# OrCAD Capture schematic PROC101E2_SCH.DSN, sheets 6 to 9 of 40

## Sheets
6 29. CAN & DISPLAY INTERFACE: size C; title: CAN & DISPLAY INTERFACE; note: MS_TI_MAXIE_APPLICATION_CARD_SCH_REVA
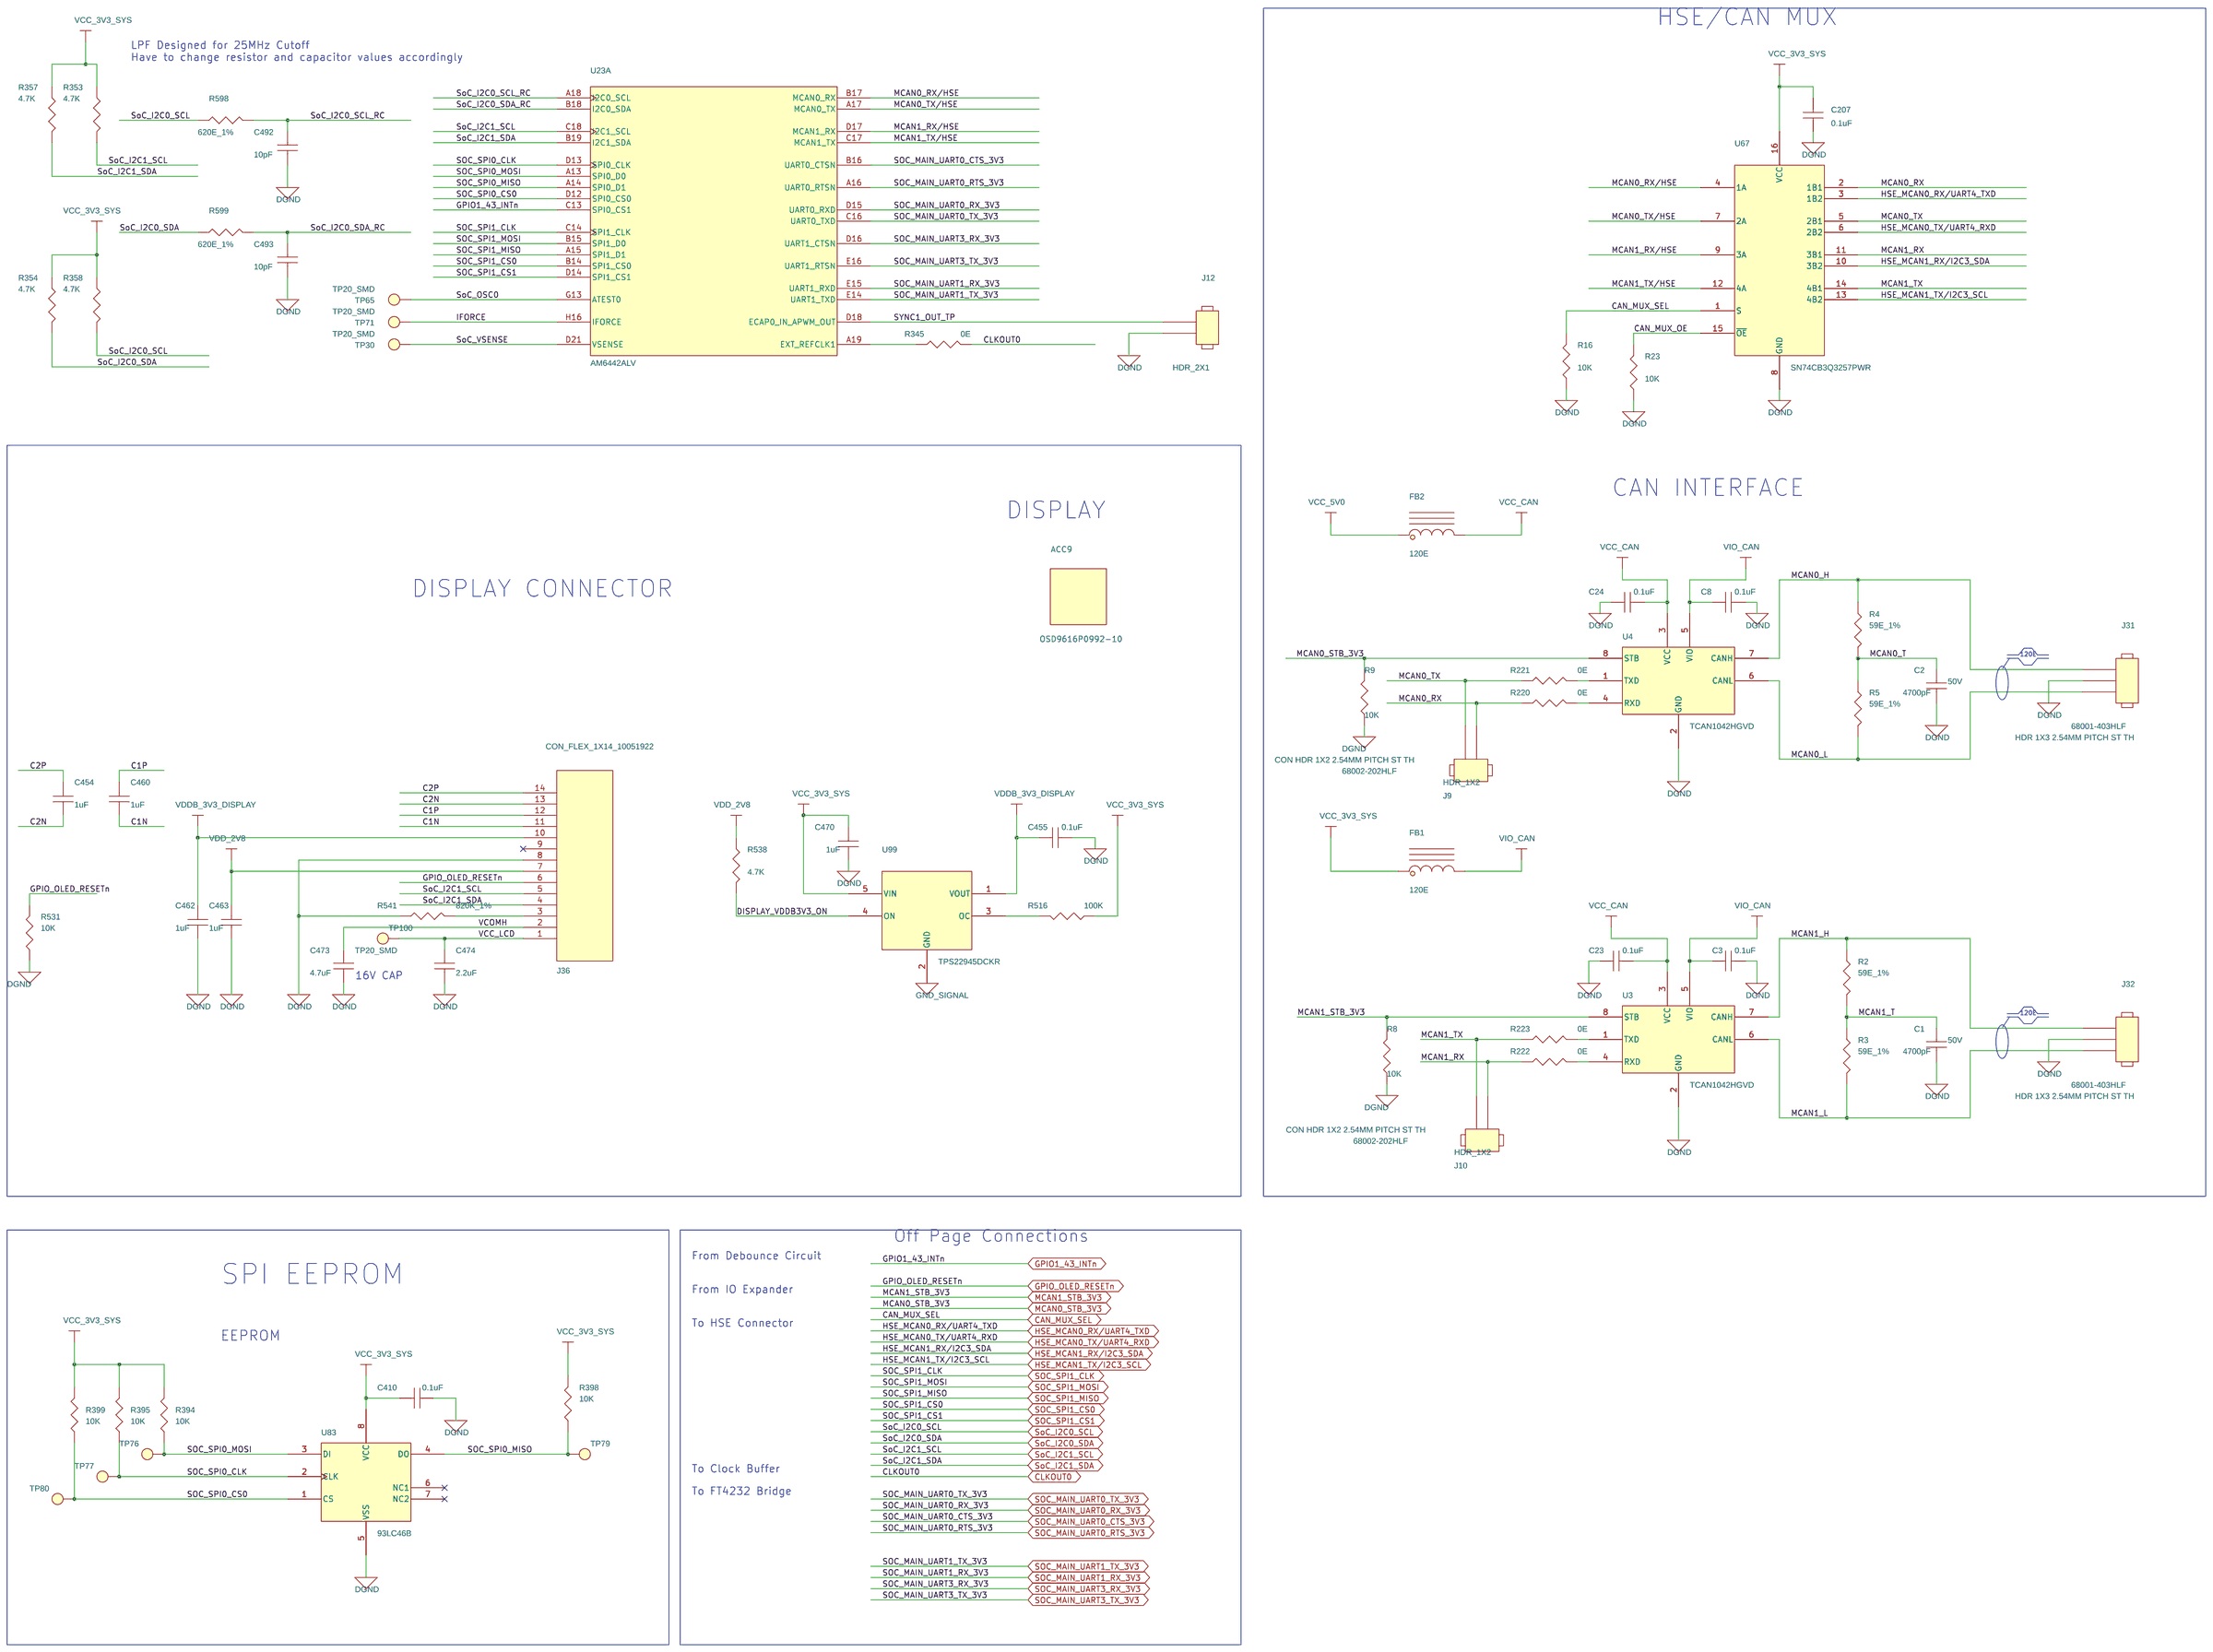
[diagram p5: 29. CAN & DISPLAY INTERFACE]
7 32.ETHERNET LED's&ADC CONNECTOR: size C; title: ETHERNET LEDs
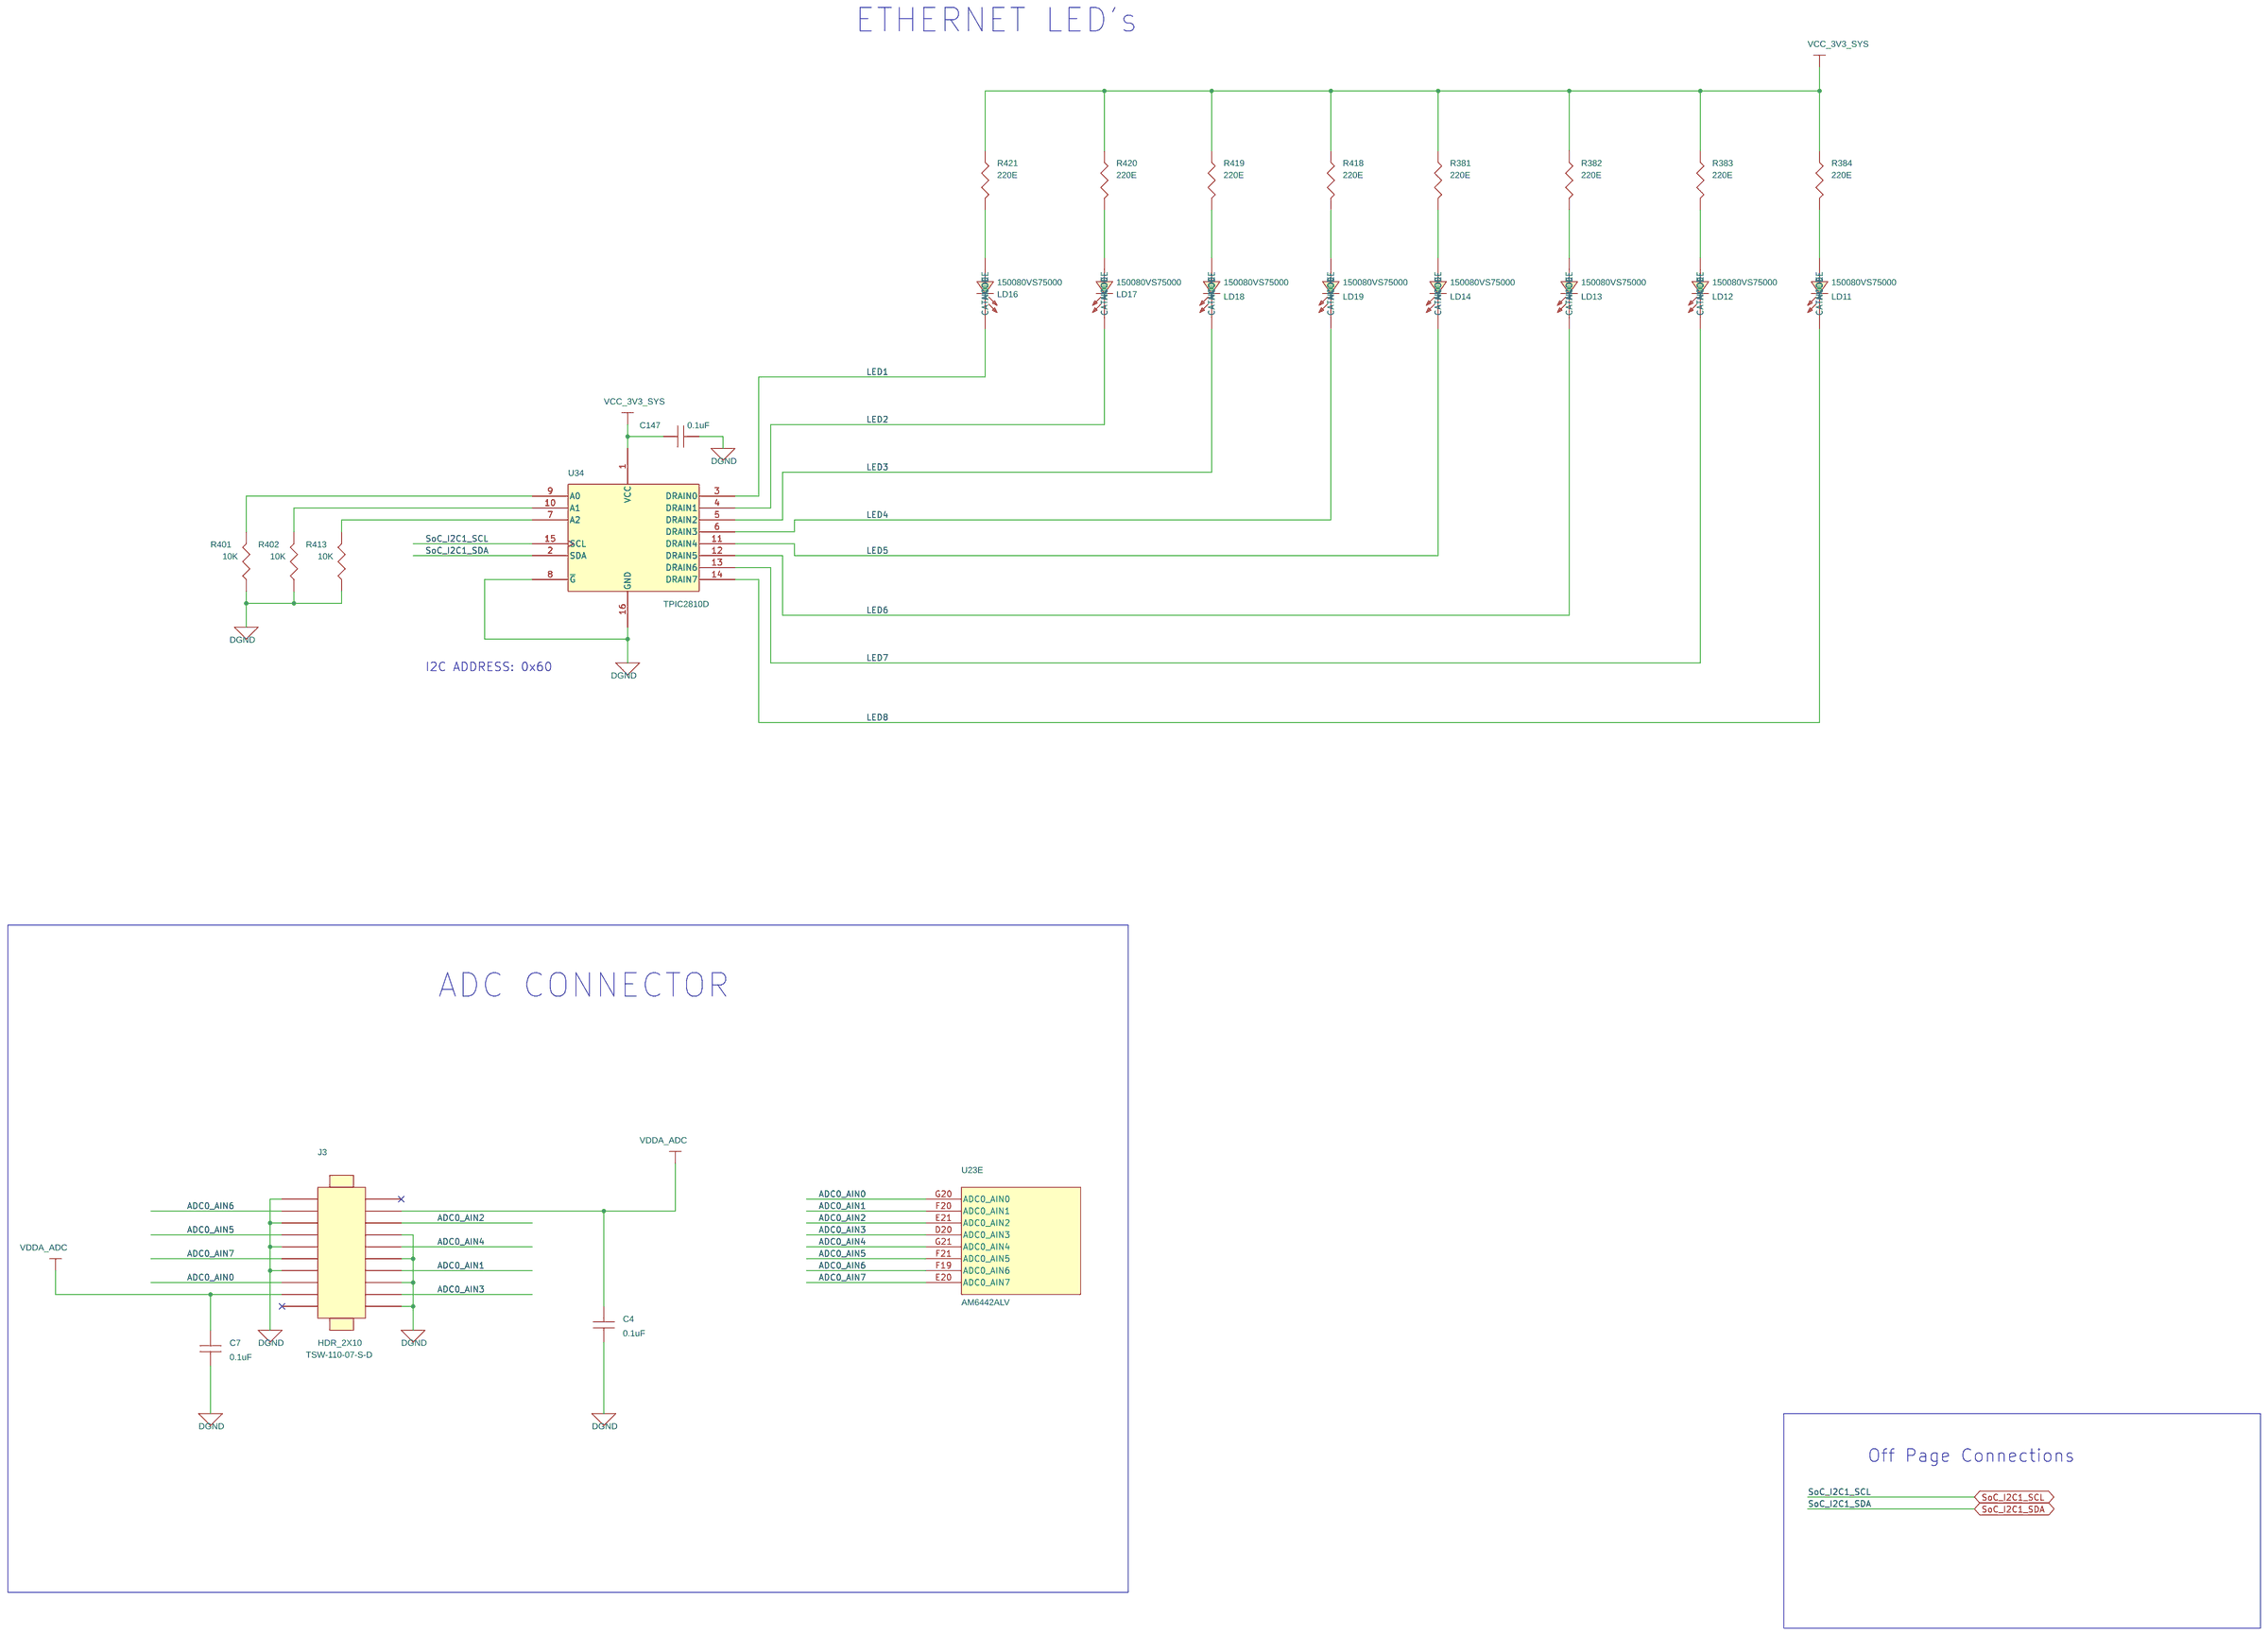
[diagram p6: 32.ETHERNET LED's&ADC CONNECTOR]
8 36. MAIN INPUT 12V DC: size C; title: MAIN 12V POWERSUPPLY
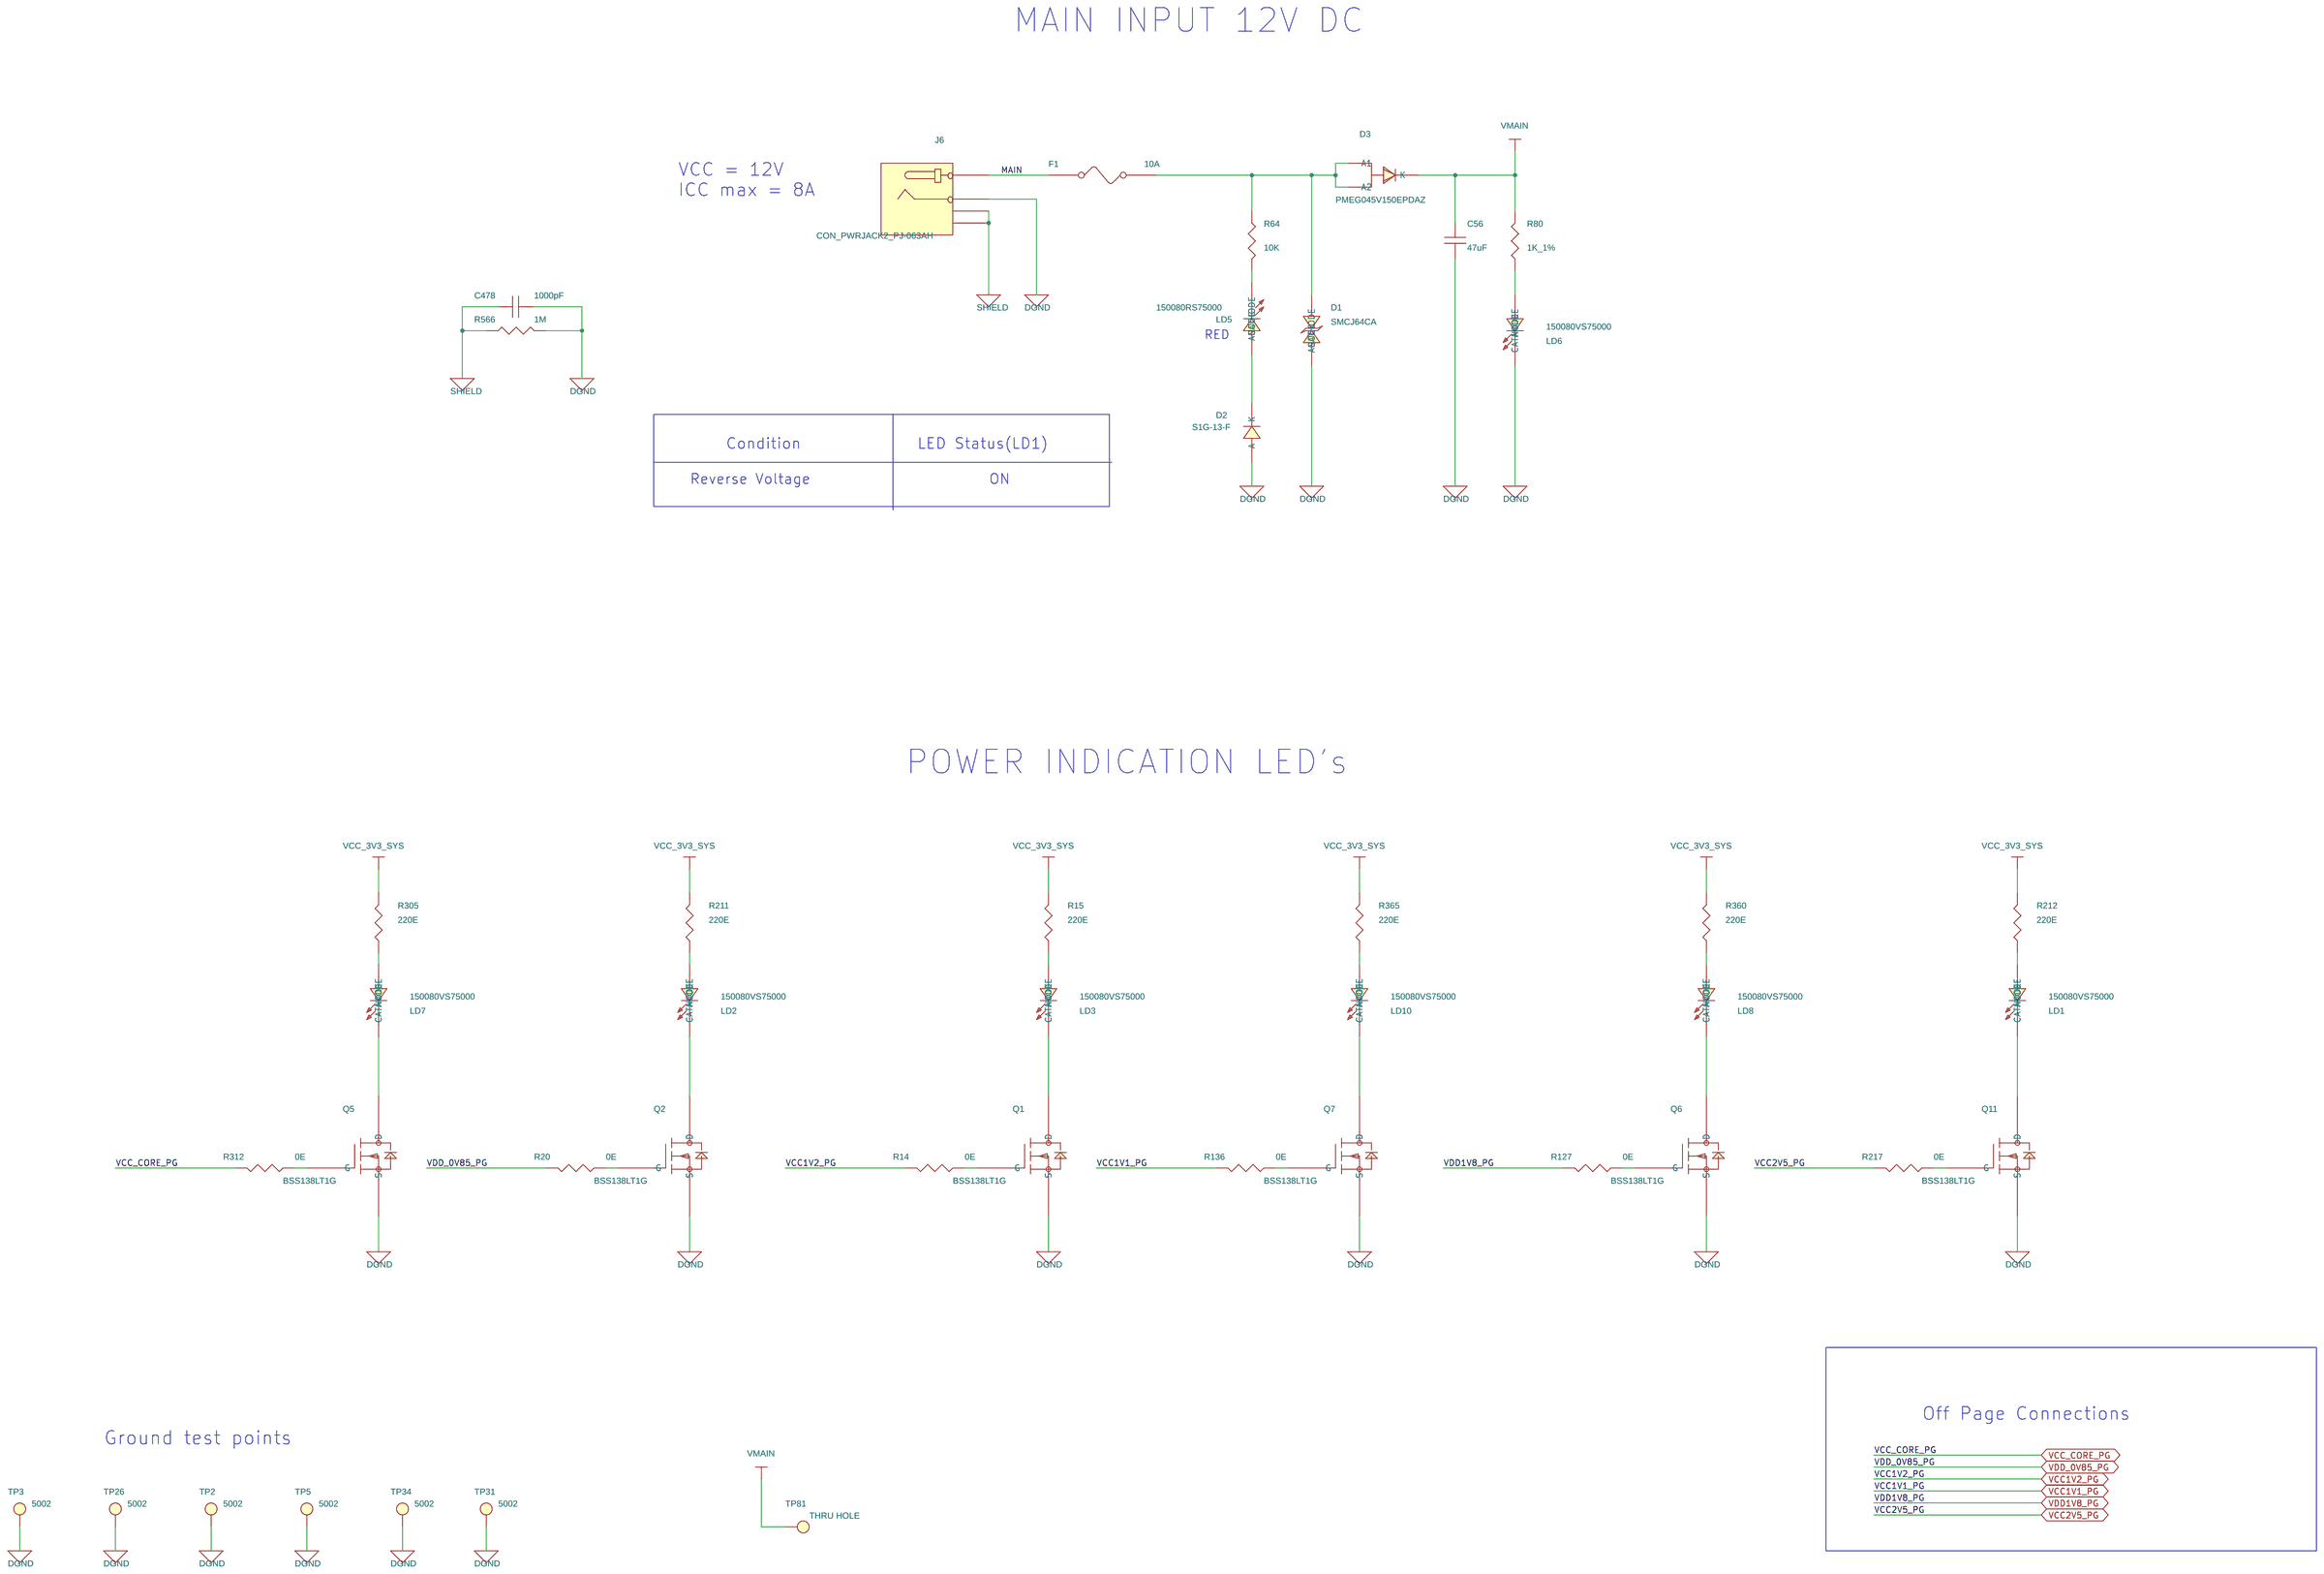
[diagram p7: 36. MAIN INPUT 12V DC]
9 11.SOC VSS: size C; title: SOC VSS
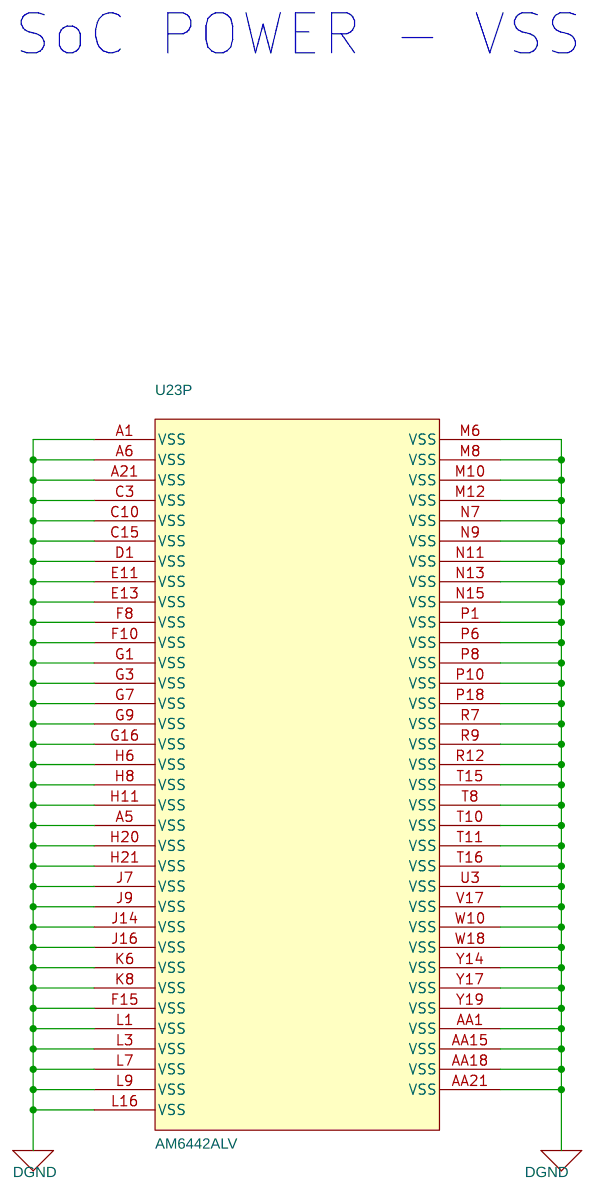
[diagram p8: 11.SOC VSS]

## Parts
sheet 11.SOC VSS
U23  AM6442ALV  [FCBGA441_31-49_680X680_2-6]  (sections A,B,C,D,E,F,G,H,I,J,K,L,M,N,O,P)
sheet 29. CAN & DISPLAY INTERFACE
ACC9  OSD9616P0992-10  [NA]
C1  4700pF  [CAP0402_0-75]
C2  4700pF  [CAP0402_0-75]
C3  0.1uF  [CAP0402_0-75]
C8  0.1uF  [CAP0402_0-75]
C23  0.1uF  [CAP0402_0-75]
C24  0.1uF  [CAP0402_0-75]
C207  0.1uF  [CAP0402_0-75]
C410  0.1uF  [CAP0402_0-75]
C454  1uF  [CAP0402_0-75]
C455  0.1uF  [CAP0402_0-75]
C460  1uF  [CAP0402_0-75]
C462  1uF  [CAP0402_0-75]
C463  1uF  [CAP0402_0-75]
C470  1uF  [CAP0402_0-75]
C473  4.7uF  [CAP0603_1]
C474  2.2uF  [CAP0603_1]
C492  10pF  [CAP0402_0-75]
C493  10pF  [CAP0402_0-75]
FB1  120E  [IND0603_1]
FB2  120E  [IND0603_1]
J9  HDR_1X2  [HDR_1X2_68002-202_S_T_8-6]
J10  HDR_1X2  [HDR_1X2_68002-202_S_T_8-6]
J12  HDR_2X1  [HDR_2X1_100_S_T]
J31  HDR_1X3  [HDR_3X1_100_S_T]
J32  HDR_1X3  [HDR_3X1_100_S_T]
J36  CON_FLEX_1X14_10051922  [CON_FLEX1X14_10051922_S_R_S]
R2  59E_1%  [RES0402_0-5]
R3  59E_1%  [RES0402_0-5]
R4  59E_1%  [RES0402_0-5]
R5  59E_1%  [RES0402_0-5]
R8  10K  [RES0402_0-5]
R9  10K  [RES0402_0-5]
R16  10K  [RES0402_0-5]
R23  10K  [RES0402_0-5]
R220  0E  [RES0402_0-5]
R221  0E  [RES0402_0-5]
R222  0E  [RES0402_0-5]
R223  0E  [RES0402_0-5]
R345  0E  [RES0402_0-5]
R353  4.7K  [RES0402_0-5]
R354  4.7K  [RES0402_0-5]
R357  4.7K  [RES0402_0-5]
R358  4.7K  [RES0402_0-5]
R394  10K  [RES0402_0-5]
R395  10K  [RES0402_0-5]
R398  10K  [RES0402_0-5]
R399  10K  [RES0402_0-5]
R516  100K  [RES0402_0-5]
R531  10K  [RES0402_0-5]
R538  4.7K  [RES0402_0-5]
R541  820K_1%  [RES0402_0-5]
R598  620E_1%  [RES0402_0-5]
R599  620E_1%  [RES0402_0-5]
TP30  TP20_SMD  [TP20_SMD]
TP65  TP20_SMD  [TP20_SMD]
TP71  TP20_SMD  [TP20_SMD]
TP76  TP20_SMD  [TP20_SMD]
TP77  TP20_SMD  [TP20_SMD]
TP79  TP20_SMD  [TP20_SMD]
TP80  TP20_SMD  [TP20_SMD]
TP100  TP20_SMD  [TP20_SMD]
U3  TCAN1042HGVD  [SOIC8_1-8]
U4  TCAN1042HGVD  [SOIC8_1-8]
U67  SN74CB3Q3257PWR  [TSSOP16_25-59_205X180]
U83  93LC46B  [MSOP8_25-59_125X125_1-1]
U99  TPS22945DCKR  [SC70-5_1-1]
sheet 32.ETHERNET LED's&ADC CONNECTOR
C4  0.1uF  [CAP0402_0-75]
C7  0.1uF  [CAP0402_0-75]
C147  0.1uF  [CAP0402_0-75]
J3  HDR_2X10  [HDR_2X10_TSW_100_S_T]
LD11  150080VS75000  [LED_150080VS75000_80X50_SMD_0-8]
LD12  150080VS75000  [LED_150080VS75000_80X50_SMD_0-8]
LD13  150080VS75000  [LED_150080VS75000_80X50_SMD_0-8]
LD14  150080VS75000  [LED_150080VS75000_80X50_SMD_0-8]
LD16  150080VS75000  [LED_150080VS75000_80X50_SMD_0-8]
LD17  150080VS75000  [LED_150080VS75000_80X50_SMD_0-8]
LD18  150080VS75000  [LED_150080VS75000_80X50_SMD_0-8]
LD19  150080VS75000  [LED_150080VS75000_80X50_SMD_0-8]
R381  220E  [RES0402_0-5]
R382  220E  [RES0402_0-5]
R383  220E  [RES0402_0-5]
R384  220E  [RES0402_0-5]
R401  10K  [RES0402_0-5]
R402  10K  [RES0402_0-5]
R413  10K  [RES0402_0-5]
R418  220E  [RES0402_0-5]
R419  220E  [RES0402_0-5]
R420  220E  [RES0402_0-5]
R421  220E  [RES0402_0-5]
U34  TPIC2810D  [SOIC16_1-8]
sheet 36. MAIN INPUT 12V DC
C56  47uF  [CAP1206_2]
C478  1000pF  [CAP1206_1-75]
D1  SMCJ64CA  [DIO_SMC]
D2  S1G-13-F  [DIO_SMA]
D3  PMEG045V150EPDAZ  [CFP15_PMEG045V150EPD_0-9]
F1  10A  [FUSE_397_410X110_SMD_2-9]
J6  CON_PWRJACK2_PJ-063AH  [CON_PWRJACK2_PJ-063AH_P_R_T_9]
LD1  150080VS75000  [LED_150080VS75000_80X50_SMD_0-8]
LD2  150080VS75000  [LED_150080VS75000_80X50_SMD_0-8]
LD3  150080VS75000  [LED_150080VS75000_80X50_SMD_0-8]
LD5  150080RS75000  [LED_150080VS75000_80X50_SMD_0-8]
LD6  150080VS75000  [LED_150080VS75000_80X50_SMD_0-8]
LD7  150080VS75000  [LED_150080VS75000_80X50_SMD_0-8]
LD8  150080VS75000  [LED_150080VS75000_80X50_SMD_0-8]
LD10  150080VS75000  [LED_150080VS75000_80X50_SMD_0-8]
Q1  BSS138LT1G  [SOT23-123_1-2]
Q2  BSS138LT1G  [SOT23-123_1-2]
Q5  BSS138LT1G  [SOT23-123_1-2]
Q6  BSS138LT1G  [SOT23-123_1-2]
Q7  BSS138LT1G  [SOT23-123_1-2]
Q11  BSS138LT1G  [SOT23-123_1-2]
R14  0E  [RES0402_0-5]
R15  220E  [RES0402_0-5]
R20  0E  [RES0402_0-5]
R64  10K  [RES1206_0-75]
R80  1K_1%  [RES0402_0-5]
R127  0E  [RES0402_0-5]
R136  0E  [RES0402_0-5]
R211  220E  [RES0402_0-5]
R212  220E  [RES0402_0-5]
R217  0E  [RES0402_0-5]
R305  220E  [RES0402_0-5]
R312  0E  [RES0402_0-5]
R360  220E  [RES0402_0-5]
R365  220E  [RES0402_0-5]
R566  1M  [RES0603_0-75]
TP2  5002  [TP_CIR67D40_TH_4-6]
TP3  5002  [TP_CIR67D40_TH_4-6]
TP5  5002  [TP_CIR67D40_TH_4-6]
TP26  5002  [TP_CIR67D40_TH_4-6]
TP31  5002  [TP_CIR67D40_TH_4-6]
TP34  5002  [TP_CIR67D40_TH_4-6]
TP81  THRU HOLE  [TP_40X65]

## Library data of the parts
U23 = AM64-SVB_BGA441: IC AM64 SoC MICROPROCESSOR BGA441; Chkd/date: MANIRAJA/020520; Crtd /date: ALVY/090420; Custom_Duty: 15%; Customs_HS_Code: 85423100; Distributor_name: NA; Distributor_part_number: NA; Footprint Path: Y:\MIS_DATABASE\Library\ALTIUM_TOOL\PCB_FOOTPRINTS\Altium_Footprint_Lib.PcbLib; Height: 2.57MM; Library Path: Y:\MIS_DATABASE\Library\ALTIUM_TOOL\SCHEMATICS_PARTS\MS_MICROPROCESSOR_Library.schlib; Mfr_name: TEXAS INSTRUMENTS; Mfr_part_number: AM6442ASFGGAALV; Mistral Part No: 141220040002; Package: BGA441; Part_type: ICS\DIGITAL\MICROPROCESSOR; Project: AM64x_SVB BRD; RoHS: NA; Temperature: NA; Tolerance: NA; Voltage: NA; Wattage: NA; Weight: NA; Datasheet: Y:\MIS_DATABASE\DATASHEETS\ICS\DIGITAL\MICROCONTROLLER\AM64-SoC_SVB.PDF
ACC9 = ACCESSORY: ACCESSORIE PASSIVE MATRIX LIGHT BLUE MONOCHROME DISPLAY; Chkd/date: MANIRAJA/270520; Crtd /date: ALVY/250520; Mfr_name: OSD DISPLAYS; Mistral Part No: 160020050021; Part_type: ACCESSORIES; Project: AM64x-GP_EVM BRD; Temperature: -40°C+70°C; Weight: 720mg; Datasheet: Y:\MIS_DATABASE\DATASHEETS\MISC\ACCESSORIES\OSD9616P0992-10.PDF
C1 C2 = CAP: CAP CERAMIC 4700pF 50V 10% X7R 0402; Chkd/date: MANIRAJA/170820; Crtd /date: ALVY/170820; Custom_Duty: 15%; Customs_HS_Code: 85322990; Distributor_name: DIGIKEY; Distributor_part_number: 732-7560-1-ND; Footprint Path: Y:\MIS_DATABASE\Library\ALTIUM_TOOL\PCB_FOOTPRINTS\Altium_Footprint_Lib.PcbLib; Height: 0.55MM; Library Path: Y:\MIS_DATABASE\Library\ALTIUM_TOOL\SCHEMATICS_PARTS\MS_DISCRETE_Library.schlib; Mfr_name: WURTH ELECTRONICS; Mfr_part_number: 885012205065; Mistral Part No: 120009030440-R; Package: 0402; Part_type: CAPACITORS\CERAMIC; Project: AM64x_EVM_BRD; RoHS: RoHS; Temperature: -55°C+125°C; Tolerance: 10%; Voltage: 50V; Wattage: NA; Weight: 12mg; Datasheet: Y:\MIS_DATABASE\DATASHEETS\CAPACITORS\885012205065.PDF
C3 C4 C7 C8 C23 C24 C147 C207 C410 C455 = CAP: CAP CERAMIC 0.1uF 25V 20% X5R 0402; Alt_Mfr_name: YAGEO AMERICA; Alt_Mfr_part_number: CC0402KRX5R8BB104; Chkd/date: MANIRAJA/170820; Crtd /date: ALVY/170820; Custom_Duty: 15%; Customs_HS_Code: 85322990; Distributor_name: DIGIKEY; Distributor_part_number: 732-7495-1-ND; Footprint Path: Y:\MIS_DATABASE\Library\ALTIUM_TOOL\PCB_FOOTPRINTS\Altium_Footprint_Lib.PcbLib; Height: 0.55MM; Library Path: Y:\MIS_DATABASE\Library\ALTIUM_TOOL\SCHEMATICS_PARTS\MS_DISCRETE_Library.schlib; Mfr_name: WURTH ELECTRONICS; Mfr_part_number: 885012105018; Mistral Part No: 120020080003-R; Package: 0402; Part_type: CAPACITORS\CERAMIC; Project: AM64x_EVM_BRD; RoHS: RoHS; Temperature: -55°C+85°C; Tolerance: 20%; Voltage: 25V; Wattage: NA; Weight: 0.65mg; Datasheet: Y:\MIS_DATABASE\DATASHEETS\CAPACITORS\885012105018.PDF
C454 C460 C462 C463 C470 = CAP: CAP CERAMIC 1uF 10V 20% X5R 0402; Chkd/date: MANIRAJA/210820; Crtd /date: ALVY/190820; Custom_Duty: 15%; Customs_HS_Code: 85322990; Distributor_name: DIGIKEY; Distributor_part_number: 732-7489-1-ND; Footprint Path: Y:\MIS_DATABASE\Library\ALTIUM_TOOL\PCB_FOOTPRINTS\Altium_Footprint_Lib.PcbLib; Height: 0.55MM; Library Path: Y:\MIS_DATABASE\Library\ALTIUM_TOOL\SCHEMATICS_PARTS\MS_DISCRETE_Library.schlib; Mfr_name: WURTH ELECTRONICS; Mfr_part_number: 885012105012; Mistral Part No: 120020080009-R; Package: 0402; Part_type: CAPACITORS\CERAMIC; Project: AM64x_EVM_BRD; RoHS: RoHS; Temperature: -55°C+85°C; Tolerance: 20%; Voltage: 10V; Wattage: NA; Weight: 0.65mg; Datasheet: Y:\MIS_DATABASE\DATASHEETS\CAPACITORS\885012105012.PDF
C473 = CAP: CAP CERAMIC 4.7uF 16V 10% X5R 0603; Chkd/date: MANIRAJA/131217; Crtd /date: ALVY/131217; Custom_Duty: 15%; Customs_HS_Code: 85322990; Distributor_name: DIGIKEY; Distributor_part_number: 311-1785-1-ND; Footprint Path: Y:\MIS_DATABASE\Library\ALTIUM_TOOL\PCB_FOOTPRINTS\Altium_Footprint_Lib.PcbLib; Height: 0.95MM; Library Path: Y:\MIS_DATABASE\Library\ALTIUM_TOOL\SCHEMATICS_PARTS\MS_DISCRETE_Library.schlib; Mfr_name: YAGEO AMERICA; Mfr_part_number: CC0603KRX5R7BB475; Mistral Part No: 120011050004-R; Package: 0603; Part_type: CAPACITORS\CERAMIC; Project: ASL_LIU_TYPE-II; RoHS: RoHS; Temperature: -55°C+85°C; Tolerance: 10%; Voltage: 16V; Wattage: NA; Weight: 2mg; Datasheet: Y:\MIS_DATABASE\DATASHEETS\CAPACITORS\YACC-X5R.PDF
C474 = CAP: CAP CERAMIC 2.2uF 35V 10% X5R 0603; Chkd/date: VASANTHA/270117; Crtd /date: MANIRAJA/270117; Custom_Duty: 15%; Customs_HS_Code: 85322990; Distributor_name: DIGIKEY; Distributor_part_number: 490-7204-1-ND; Footprint Path: Y:\MIS_DATABASE\Library\ALTIUM_TOOL\PCB_FOOTPRINTS\Altium_Footprint_Lib.PcbLib; Height: 0.90MM; Library Path: Y:\MIS_DATABASE\Library\ALTIUM_TOOL\SCHEMATICS_PARTS\MS_DISCRETE_Library.schlib; Mfr_name: MURATA; Mfr_part_number: GRM188R6YA225KA12D; Mistral Part No: 120017010016-R; Package: 0603; Part_type: CAPACITORS\CERAMIC; Project: SD820_NANO_SOM; RoHS: RoHS; Temperature: -55°C+85°C; Tolerance: 10%; Voltage: 35V; Wattage: NA; Weight: 6.3mg; Datasheet: Y:\MIS_DATABASE\DATASHEETS\CAPACITORS\MURATA-GXX-SER_NOV17.PDF
C492 C493 = CAP: CAP CERAMIC 10pF 16V 5% C0G(NP0) 0402; Chkd/date: MANIRAJA/100918; Crtd /date: ALVY/100918; Custom_Duty: 15%; Customs_HS_Code: 85322990; Distributor_name: DIGIKEY; Distributor_part_number: 732-7441-1-ND; Footprint Path: Y:\MIS_DATABASE\Library\ALTIUM_TOOL\PCB_FOOTPRINTS\Altium_Footprint_Lib.PcbLib; Height: 0.55MM; Library Path: Y:\MIS_DATABASE\Library\ALTIUM_TOOL\SCHEMATICS_PARTS\MS_DISCRETE_Library.schlib; Mfr_name: WURTH ELECTRONICS; Mfr_part_number: 885012005025; Mistral Part No: 120018030015-R; Package: 0402; Part_type: CAPACITORS\CERAMIC; Project: SMART-M_SCRIPTALK_PB; RoHS: RoHS; Temperature: -55°C+125°C; Tolerance: 5%; Voltage: 16V; Wattage: NA; Weight: 0.65mg; Datasheet: Y:\MIS_DATABASE\DATASHEETS\CAPACITORS\885012005025.PDF
FB1 FB2 = INDUCTOR_FERRITE: IND FERRITE BEAD CHIP 120E 2A 0603; Chkd/date: MANIRAJA/180820; Crtd /date: ALVY/180820; Custom_Duty: 24%; Customs_HS_Code: 85437099; Distributor_name: DIGIKEY; Distributor_part_number: 732-782631141CT-ND; Footprint Path: Y:\MIS_DATABASE\Library\ALTIUM_TOOL\PCB_FOOTPRINTS\Altium_Footprint_Lib.PcbLib; Height: 1.00MM; Library Path: Y:\MIS_DATABASE\Library\ALTIUM_TOOL\SCHEMATICS_PARTS\MS_FILTER_Library.schlib; Mfr_name: WURTH ELECTRONICS; Mfr_part_number: 782631141; Mistral Part No: 130020080015-R; Package: 0603; Part_type: INDUCTOR; Project: AM64x_EVM_BRD; RoHS: RoHS; Temperature: -55°C+125°C; Tolerance: 25%; Voltage: NA; Wattage: NA; Weight: NA; Datasheet: Y:\MIS_DATABASE\DATASHEETS\DISCRETES\INDUCTORS\782631141.PDF
J9 J10 = HEADER_2X1: CON HDR 1X2 2.54MM PITCH ST TH; Chkd/date: MANIRAJA/190118; Crtd /date: ALVY/190118; Custom_Duty: 24%; Customs_HS_Code: 85369090; Distributor_name: DIGIKEY; Distributor_part_number: 68002-202HLF-ND; Height: 8.58MM; Mfr_name: AMPHENOL; Mfr_part_number: 68002-202HLF; Mistral Part No: 150018010012-R; Package: THRU HOLE; Part_type: CONNECTOR\HEADERS; Project: TI_SVB_MAXWELL_DUT; RoHS: RoHS; Temperature: NA; Tolerance: NA; Voltage: NA; Wattage: NA; Weight: NA; Datasheet: Y:\MIS_DATABASE\DATASHEETS\CONNECTORS\68002.PDF
J12 = HEADER_2X1: CON HDR 2X1 2.54MM PITCH ST TH; Chkd/date: NAVEED/210714; Crtd /date: USMAN/031012; Custom_Duty: 24%; Customs_HS_Code: 85369090; Distributor_name: DIGIKEY; Distributor_part_number: WM8072-ND; Height: 5.60MM; Mfr_name: MOLEX; Mfr_part_number: 90120-0122; Mistral Part No: 150012100005-R; Package: THRU-HOLE; Part_type: CONNECTOR\HEADERS; Project: NPOL_FEP; RoHS: RoHS; Temperature: -55°C+125°C; Tolerance: NA; Voltage: NA; Wattage: NA; Weight: NA; Datasheet: Y:\MIS_DATABASE\DATASHEETS\CONNECTORS\90120-SERIES.PDF
J31 J32 = HEADER_3X1: HDR 1X3 2.54MM PITCH ST TH; Chkd/date: VASANTHA/290616; Crtd /date: VASANTHA/290616; Custom_Duty: 15%; Customs_HS_Code: 85322990; Distributor_name: DIGIKEY; Distributor_part_number: 609-3471-ND; Height: 8.58MM; Mfr_name: FCI; Mfr_part_number: 68001-403HLF; Mistral Part No: 150016060025-R; Package: THRU-HOLE; Part_type: CONNECTOR\HEADERS; Project: IKEYP; RoHS: RoHS; Temperature: -40°C+105°C; Tolerance: NA; Voltage: NA; Wattage: NA; Weight: NA; Datasheet: Y:\MIS_DATABASE\DATASHEETS\CONNECTORS\68000.PDF
J36 = CON_FLEX_14X1_FH19: CON FPC 1X14 0.50MM PITCH RT SMD; Chkd/date: VASANTHA/261115; Crtd /date: VASANTHA/261115; Custom_Duty: 24%; Customs_HS_Code: 85369090; Distributor_name: DIGIKEY; Distributor_part_number: 609-1237-1-ND; Height: 1.50MM; Mfr_name: FCI; Mfr_part_number: 10051922-1410ELF; Mistral Part No: 150015110023-R; Package: SMD; Part_type: CONNECTOR\FPC; Project: TI_C5545; RoHS: RoHS; Temperature: NA; Tolerance: NA; Voltage: NA; Wattage: NA; Weight: NA; Datasheet: Y:\MIS_DATABASE\DATASHEETS\CONNECTORS\10051922.PDF
R2-R5 = RESISTOR: RES 59E 1/10W 1% 0402; Chkd/date: MAZHAR/151208; Crtd /date: USMAN/031208; Custom_Duty: 15%; Customs_HS_Code: 85332119; Distributor_name: DIGIKEY; Distributor_part_number: P59.0LCT-ND; Footprint Path: Y:\MIS_DATABASE\Library\ALTIUM_TOOL\PCB_FOOTPRINTS\Altium_Footprint_Lib.PcbLib; Height: 0.40MM; Library Path: Y:\MIS_DATABASE\Library\ALTIUM_TOOL\SCHEMATICS_PARTS\MS_DISCRETE_Library.schlib; Mfr_name: PANASONIC-ECG; Mfr_part_number: ERJ-2RKF59R0X; Mistral Part No: 110009031010-R; Package: 0402; Part_type: RESISTORS\FIXED; Project: KHAN_HSST; RoHS: RoHS; Temperature: -55°C+155°C; Tolerance: 1%; Voltage: NA; Wattage: 1/10W; Weight: 0.8mg; Datasheet: Y:\MIS_DATABASE\DATASHEETS\RESISTORS\PAN-ERJSER_NOV17.PDF
R8 R9 R16 R23 R394 R395 R398 R399 R401 R402 R413 R531 = RESISTOR: RES 10K 1/16W 5% 0402; Chkd/date: VASANTHA/061216; Crtd /date: MAZHAR/230805; Custom_Duty: 15%; Customs_HS_Code: 85332119; Distributor_name: DIGIKEY; Distributor_part_number: 311-10KJRCT-ND; Footprint Path: Y:\MIS_DATABASE\Library\ALTIUM_TOOL\PCB_FOOTPRINTS\Altium_Footprint_Lib.PcbLib; Height: 0.40MM; Library Path: Y:\MIS_DATABASE\Library\ALTIUM_TOOL\SCHEMATICS_PARTS\MS_DISCRETE_Library.schlib; Mfr_name: YAGEO AMERICA; Mfr_part_number: RC0402JR-0710KL; Mistral Part No: 110011060021-R; Package: 0402; Part_type: RESISTORS\FIXED; Project: HSE; RoHS: RoHS; Temperature: -55°C+155°C; Tolerance: 5%; Voltage: NA; Wattage: 1/16W; Weight: 0.65mg; Datasheet: Y:\MIS_DATABASE\DATASHEETS\RESISTORS\RCXXXXL-SER_MAR18.PDF
R14 R20 R127 R136 R217 R220-R223 R312 R345 = RESISTOR: RES 0E 1/16W JUMPER 0402; Chkd/date: VASANTHA/201216; Crtd /date: MUDDU/190810; Custom_Duty: 15%; Customs_HS_Code: 85332119; Distributor_name: DIGIKEY; Distributor_part_number: 541-0.0JCT-ND; Footprint Path: Y:\MIS_DATABASE\Library\ALTIUM_TOOL\PCB_FOOTPRINTS\Altium_Footprint_Lib.PcbLib; Height: 0.40MM; Library Path: Y:\MIS_DATABASE\Library\ALTIUM_TOOL\SCHEMATICS_PARTS\MS_DISCRETE_Library.schlib; Mfr_name: VISHAY; Mfr_part_number: CRCW04020000Z0ED; Mistral Part No: 110010080019-R; Package: 0402; Part_type: RESISTORS\FIXED; Project: PB_BUGBASE; RoHS: RoHS; Temperature: -55°C+155°C; Tolerance: NA; Voltage: NA; Wattage: 1/16W; Weight: 0.65mg; Datasheet: Y:\MIS_DATABASE\DATASHEETS\RESISTORS\CRCW0603.PDF
R353 R354 R357 R358 R538 = RESISTOR: RES 4.7K 1/16W 5% 0402; Chkd/date: VASANTHA/130516; Crtd /date: VASANTHA/130516; Custom_Duty: 15%; Customs_HS_Code: 85332119; Distributor_name: DIGIKEY; Distributor_part_number: 311-4.7KJRCT-ND; Footprint Path: Y:\MIS_DATABASE\Library\ALTIUM_TOOL\PCB_FOOTPRINTS\Altium_Footprint_Lib.PcbLib; Height: 0.40MM; Library Path: Y:\MIS_DATABASE\Library\ALTIUM_TOOL\SCHEMATICS_PARTS\MS_DISCRETE_Library.schlib; Mfr_name: YAGEO AMERICA; Mfr_part_number: RC0402JR-074K7L; Mistral Part No: 110011060001-R; Package: 0402; Part_type: RESISTORS\FIXED; Project: TMDXCSK368; RoHS: RoHS; Temperature: -55°C+155°C; Tolerance: 5%; Voltage: NA; Wattage: 1/16W; Weight: 0.65mg; Datasheet: Y:\MIS_DATABASE\DATASHEETS\RESISTORS\RCXXXXL-SER_MAR18.PDF
R516 = RESISTOR: RES 100K 1/16W 5% 0402; Chkd/date: VASANTHA/061216; Crtd /date: BAVISH/010611; Custom_Duty: 15%; Customs_HS_Code: 85332119; Distributor_name: DIGIKEY; Distributor_part_number: 541-100KJCT-ND; Footprint Path: Y:\MIS_DATABASE\Library\ALTIUM_TOOL\PCB_FOOTPRINTS\Altium_Footprint_Lib.PcbLib; Height: 0.40MM; Library Path: Y:\MIS_DATABASE\Library\ALTIUM_TOOL\SCHEMATICS_PARTS\MS_DISCRETE_Library.schlib; Mfr_name: VISHAY; Mfr_part_number: CRCW0402100KJNED; Mistral Part No: 110011060002-R; Package: 0402; Part_type: RESISTORS\FIXED; Project: AM4515_EVM_LCD; RoHS: RoHS; Temperature: -55°C+155°C; Tolerance: 5%; Voltage: NA; Wattage: 1/16W; Weight: 0.65mg; Datasheet: Y:\MIS_DATABASE\DATASHEETS\RESISTORS\CRCW0603.PDF
R541 = RESISTOR: RES 820K 1/10W 1% 0402; Chkd/date: SUHAS/270910; Crtd /date: MAZHAR/310809; Custom_Duty: 15%; Customs_HS_Code: 85332119; Distributor_name: DIGIKEY; Distributor_part_number: P820KLCT-ND; Footprint Path: Y:\MIS_DATABASE\Library\ALTIUM_TOOL\PCB_FOOTPRINTS\Altium_Footprint_Lib.PcbLib; Height: 0.40MM; Library Path: Y:\MIS_DATABASE\Library\ALTIUM_TOOL\SCHEMATICS_PARTS\MS_DISCRETE_Library.schlib; Mfr_name: PANASONIC-ECG; Mfr_part_number: ERJ-2RKF8203X; Mistral Part No: 110009080033-R; Package: 0402; Part_type: RESISTORS\FIXED; Project: BUG_BASE-II; RoHS: RoHS; Temperature: -55°C+155°C; Tolerance: 1%; Voltage: NA; Wattage: 1/10W; Weight: 0.8mg; Datasheet: Y:\MIS_DATABASE\DATASHEETS\RESISTORS\PAN-ERJSER_NOV17.PDF
R598 R599 = RESISTOR: RES 620E 1/10W 1% 0402; Chkd/date: USMAN/120313; Crtd /date: CHAITHANYA/270912; Custom_Duty: 15%; Customs_HS_Code: 85332119; Distributor_name: DIGIKEY; Distributor_part_number: P620LCT-ND; Footprint Path: Y:\MIS_DATABASE\Library\ALTIUM_TOOL\PCB_FOOTPRINTS\Altium_Footprint_Lib.PcbLib; Height: 0.40MM; Library Path: Y:\MIS_DATABASE\Library\ALTIUM_TOOL\SCHEMATICS_PARTS\MS_DISCRETE_Library.schlib; Mfr_name: PANASONIC-ECG; Mfr_part_number: ERJ-2RKF6200X; Mistral Part No: 110012090013-R; Package: 0402; Part_type: RESISTORS\FIXED; Project: ITS-CONTROLER_CARD; RoHS: RoHS; Temperature: -55°C+155°C; Tolerance: 1%; Voltage: NA; Wattage: 1/10W; Weight: 0.8mg; Datasheet: Y:\MIS_DATABASE\DATASHEETS\RESISTORS\PAN-ERJSER_NOV17.PDF
TP30 TP65 TP71 TP76 TP77 TP79 TP80 TP100 = TESTPOINT: TESTPOINT CIR 20 SMD; Chkd/date: SHREESHAIL/171006; Crtd /date: MAZHAR/171006; Custom_Duty: NA; Customs_HS_Code: NA; Distributor_name: NA; Distributor_part_number: NA; Footprint Path: Y:\MIS_DATABASE\Library\ALTIUM_TOOL\PCB_FOOTPRINTS\Altium_Footprint_Lib.PcbLib; Height: NA; Library Path: Y:\MIS_DATABASE\Library\ALTIUM_TOOL\SCHEMATICS_PARTS\MS_DISCRETE_Library.schlib; MECHANICAL 3D STEP FILE: NA; Mfr_name: LOCAL; Mistral Part No: NA; Package: SMD; Project: BT MODULE_CSRBC04; RoHS: NA; Temperature: NA; Tolerance: NA; Voltage: NA; Wattage: NA; Weight: NA; Datasheet: NA
U3 U4 = TCAN1042HGVD_SOIC8: IC FAULT PROTECTED CAN TRANSCEIVER WITH CAN FD SOIC8; Chkd/date: MANIRAJA/030717; Crtd /date: MANIRAJA/030717; Custom_Duty: 15%; Customs_HS_Code: 85423100; Distributor_name: DIGIKEY; Distributor_part_number: 296-43979-5-ND; Footprint Path: Y:\MIS_DATABASE\Library\ALTIUM_TOOL\PCB_FOOTPRINTS\Altium_Footprint_Lib.PcbLib; Height: 1.75MM; Library Path: Y:\MIS_DATABASE\Library\ALTIUM_TOOL\SCHEMATICS_PARTS\MS_TELECOM_Library.schlib; Mfr_name: TEXAS INSTRUMENTS; Mistral Part No: 143017070001-R; Package: SOIC8; Part_type: ICS\TELECOM\TRANSCEIVER; Project: TI_SVB_CONTROLLER CARD; RoHS: RoHS; Temperature: -55°C+125°C; Tolerance: NA; Voltage: NA; Wattage: NA; Weight: 540mg; Datasheet: Y:\MIS_DATABASE\DATASHEETS\ICS\DIGITAL\BUSTRANSCEIVER\TCAN1042.PDF
U67 = SN74CB3Q3257PWR_TSSOP16: IC 4BIT 1-OF-2 FET MULTIPLEXER/DEMULTIPLEXER TSSOP16; Chkd/date: SUHAS/251010; Crtd /date: USMAN/060109; Custom_Duty: 15%; Customs_HS_Code: 85423100; Distributor_name: DIGIKEY; Distributor_part_number: 296-19138-1-ND; Height: 1.20MM; Mfr_name: TEXAS INSTRUMENTS; Mistral Part No: 141009030117-R; Package: TSSOP16; Part_type: ICS\DIGITAL\COMBINATIONAL; Project: OMAP_EVM; RoHS: Sb/ Br FREE; Temperature: -40°C+85°C; Datasheet: Y:\MIS_DATABASE\DATASHEETS\ICS\DIGITAL\COMBINATIONAL\SN74CB3Q3257.PDF
U83 = 93LC46B_MSOP8: IC 1K MICROWIRE COMPATIBLE SERIAL EEPROM MSOP8; Chkd/date: MANIRAJA/150218; Crtd /date: ALVY/150218; Custom_Duty: 15%; Customs_HS_Code: 85423100; Distributor_name: DIGIKEY; Distributor_part_number: 93LC46B-I/MS-ND; Footprint Path: Y:\MIS_DATABASE\Library\ALTIUM_TOOL\PCB_FOOTPRINTS\Altium_Footprint_Lib.PcbLib; Height: 1.10MM; Library Path: Y:\MIS_DATABASE\Library\ALTIUM_TOOL\SCHEMATICS_PARTS\MS_MISCMEMORY_Library.schlib; Mfr_name: MICROCHIP; Mfr_part_number: 93LC46B-I/MS; Mistral Part No: 141118020002-R; Package: MSOP8; Part_type: ICS\DIGITAL\MEMORY; Project: TI_MAXIE_CPB; RoHS: RoHS; Temperature: -40°C+85°C; Tolerance: NA; Voltage: NA; Wattage: NA; Weight: 140mg; Datasheet: Y:\MIS_DATABASE\DATASHEETS\ICS\MEMORY\93LC46B.PDF
U99 = TPS22945DCKR_SC70-5: IC LOW INPUT VOLTAGE CURRENT LIMITED LOAD SWITCH SC70-5; Chkd/date: VASANTHA/010117; Crtd /date: USMAN/020409; Custom_Duty: 15%; Customs_HS_Code: 85423100; Distributor_name: DIGIKEY; Distributor_part_number: 296-24475-1-ND; Height: 1.10MM; Mfr_name: TEXAS INSTRUMENTS; Mistral Part No: 142009030143-R; Package: SC70-5; Part_type: ICS\POWER; Project: AXON; RoHS: RoHS; Temperature: -40°C+85°C; Tolerance: NA; Voltage: NA; Wattage: NA; Weight: 2.5mg; Datasheet: Y:\MIS_DATABASE\DATASHEETS\ICS\POWER\TPS2294.PDF
J3 = HEADER_10X2: CON HDR 2X10 2.54MM PITCH ST TH; Chkd/date: NAVEED/140515; Crtd /date: MAZHAR/020909; Custom_Duty: 0.24; Customs_HS_Code: 85369090; Distributor_name: DIGIKEY; Distributor_part_number: SAM1032-10-ND; Height: 5.02MM; Mfr_name: SAMTEC; Mfr_part_number: TSW-110-07-S-D; Mistral Part No: 150009090001-R; Package: THRU-HOLE; Part_type: CONNECTOR\HEADERS; Project: SMART VIEW_NVR; RoHS: RoHS; Temperature: NA; Tolerance: NA; Voltage: NA; Wattage: NA; Weight: NA; Datasheet: Y:\MIS_DATABASE\DATASHEETS\CONNECTORS\TSW-106-23-T-S.PDF
LD1-LD3 LD6-LD8 LD10-LD14 LD16-LD19 = DIODE_LED: DIODE LED BRIGHT GREEN SMD; Chkd/date: MANIRAJA/180820; Crtd /date: ALVY/180820; Custom_Duty: 24%; Customs_HS_Code: 85439000; Distributor_name: DIGIKEY; Distributor_part_number: 732-4986-1-ND; Footprint Path: Y:\MIS_DATABASE\Library\ALTIUM_TOOL\PCB_FOOTPRINTS\Altium_Footprint_Lib.PcbLib; Height: 0.80MM; Library Path: Y:\MIS_DATABASE\Library\ALTIUM_TOOL\SCHEMATICS_PARTS\MS_OPTO_Library.schlib; Mfr_name: WURTH ELECTRONICS; Mistral Part No: 130020080012-R; Package: SMD; Part_type: OPTO\LED; Project: AM64x_EVM_BRD; RoHS: RoHS; Temperature: -40°C+85°C; Tolerance: NA; Voltage: NA; Wattage: NA; Weight: 10mg; Datasheet: Y:\MIS_DATABASE\DATASHEETS\DISCRETES\LEDS\150080VS75000.PDF
R15 R211 R212 R305 R360 R365 R381-R384 R418-R421 = RESISTOR: RES 220E 1/10W 5% 0402; Chkd/date: VASANTHA/291216; Crtd /date: GEETHA/260406; Custom_Duty: 15%; Customs_HS_Code: 85332119; Distributor_name: DIGIKEY; Distributor_part_number: P220JCT-ND; Footprint Path: Y:\MIS_DATABASE\Library\ALTIUM_TOOL\PCB_FOOTPRINTS\Altium_Footprint_Lib.PcbLib; Height: 0.40MM; Library Path: Y:\MIS_DATABASE\Library\ALTIUM_TOOL\SCHEMATICS_PARTS\MS_DISCRETE_Library.schlib; Mfr_name: PANASONIC-ECG; Mfr_part_number: ERJ-2GEJ221X; Mistral Part No: 110009030506-R; Package: 0402; Part_type: RESISTORS\FIXED; Project: RED EYE; RoHS: RoHS; Temperature: -55°C+155°C; Tolerance: 5%; Voltage: NA; Wattage: 1/10W; Weight: 0.8mg; Datasheet: Y:\MIS_DATABASE\DATASHEETS\RESISTORS\PAN-ERJSER_NOV17.PDF
U34 = TPIC2810D_SOIC16: IC 8-BIT LED DRIVER WITH I2C INTERFACE SOIC16; Chkd/date: MANIRAJA/230817; Crtd /date: MANIRAJA/220817; Custom_Duty: 15%; Customs_HS_Code: 85423100; Distributor_name: DIGIKEY; Distributor_part_number: 296-13746-5-ND; Height: 1.75MM; Mfr_name: TEXAS INSTRUMENTS; Mistral Part No: 141017080026-R; Package: SOIC16; Part_type: ICS\INTERFACE; Project: TI_MAXIE_CPB; RoHS: RoHS; Temperature: -40°C+125°C; Tolerance: NA; Voltage: NA; Wattage: NA; Weight: NA; Datasheet: Y:\MIS_DATABASE\DATASHEETS\ICS\INTERFACE\TPIC2810D.PDF
C56 = CAP: CAP CERAMIC 47uF 25V 20% X5R 1206; Chkd/date: MANIRAJA/230118; Crtd /date: MANIRAJA/230118; Custom_Duty: 15%; Customs_HS_Code: 85322990; Distributor_name: DIGIKEY; Distributor_part_number: 490-16268-1-ND; Footprint Path: Y:\MIS_DATABASE\Library\ALTIUM_TOOL\PCB_FOOTPRINTS\Altium_Footprint_Lib.PcbLib; Height: 1.80MM; Library Path: Y:\MIS_DATABASE\Library\ALTIUM_TOOL\SCHEMATICS_PARTS\MS_DISCRETE_Library.schlib; Mfr_name: MURATA; Mfr_part_number: GRM31CR61E476ME44L; Mistral Part No: 120013050002-R; Package: 1206; Part_type: CAPACITORS\CERAMIC; Project: TI_MAXIE_CPB; RoHS: RoHS; Temperature: -55°C+85°C; Tolerance: 20%; Voltage: 25V; Wattage: NA; Weight: 40mg; Datasheet: Y:\MIS_DATABASE\DATASHEETS\CAPACITORS\MURATA-GXX-SER_NOV17.PDF
C478 = CAP: CAP CERAMIC 1000pF 2KV 10% X7R 1206; Chkd/date: SHREESHAIL/291106; Crtd /date: MAZHAR/281106; Custom_Duty: 15%; Customs_HS_Code: 85322990; Distributor_name: DIGIKEY; Distributor_part_number: 478-2956-1-ND; Footprint Path: Y:\MIS_DATABASE\Library\ALTIUM_TOOL\PCB_FOOTPRINTS\Altium_Footprint_Lib.PcbLib; Height: 1.52MM; Library Path: Y:\MIS_DATABASE\Library\ALTIUM_TOOL\SCHEMATICS_PARTS\MS_DISCRETE_Library.schlib; Mfr_name: AVX CORPORATION; Mfr_part_number: 1206GC102KAT1A; Mistral Part No: 120015080006-R; Package: 1206; Part_type: CAPACITORS\CERAMIC; Project: ADR1B; RoHS: RoHS; Temperature: -55°C+125°C; Tolerance: 10%; Voltage: 2KV; Wattage: NA; Weight: 16.2mg; Datasheet: Y:\MIS_DATABASE\DATASHEETS\CAPACITORS\AVX_HV-MLC.PDF
D1 = DIODE_TVS_DUAL: DIODE TVS BI-DIE 1500W 64V SMC; Chkd/date: VASANTHA/101015; Crtd /date: VASANTHA/101015; Custom_Duty: 15%; Customs_HS_Code: 85412900; Distributor_name: DIGIKEY; Distributor_part_number: SMCJ64CALFCT-ND; Height: 2.62MM; Mfr_name: LITTLE FUSE; Mistral Part No: 130015100009-R; Package: SMC; Part_type: DIODE\TVS; Project: GALILEO_EVM; RoHS: RoHS; Temperature: -55°C+150°C; Tolerance: NA; Voltage: 64V; Wattage: NA; Weight: NA; Datasheet: Y:\MIS_DATABASE\DATASHEETS\DISCRETES\DIODES\LTFUSE-SMCJ.PDF
D2 = DIODE: DIODE RECTIFIER 400V 1A SMA; Chkd/date: SUHAS/061010; Crtd /date: USMAN/220808; Custom_Duty: 15%; Customs_HS_Code: 85412900; Distributor_name: DIGIKEY; Distributor_part_number: S1G-FDICT-ND; Height: 2.30MM; Mfr_name: DIODES INC; Mistral Part No: 130009030153; Package: SMA; Part_type: DIODE\RECTIFIER; Project: CPB; Temperature: -65°C+150°C; Voltage: 400V; Weight: 0.0064g; Datasheet: Y:\MIS_DATABASE\DATASHEETS\DISCRETES\DIODES\S1.PDF
D3 = DIODE_SCHOTTKY_POWERMITE-3: DIODE SCHOTTKY RECTIFIER 45V 15A CFP15 (SOT1289); Chkd/date: MANIRAJA/070220; Crtd /date: ALVY/070220; Custom_Duty: 15%; Customs_HS_Code: 85412900; Distributor_name: DIGIKEY; Distributor_part_number: 1727-1905-1-ND; Footprint Path: Y:\MIS_DATABASE\Library\ALTIUM_TOOL\PCB_FOOTPRINTS\Altium_Footprint_Lib.PcbLib; Height: 0.82MM; Library Path: Y:\MIS_DATABASE\Library\ALTIUM_TOOL\SCHEMATICS_PARTS\MS_DISCRETE_Library.schlib; Mfr_name: NEXPERIA; Mistral Part No: 130020020003-R; Package: CFP15; Part_type: DIODE\SCHOTTKY; Project: TI_MAXIE_CPB; RoHS: RoHS; Temperature: -55°C+175°C; Tolerance: NA; Voltage: NA; Wattage: NA; Weight: 87.3mg; Datasheet: Y:\MIS_DATABASE\DATASHEETS\DISCRETES\DIODES\PMEG045V150EPD.PDF
F1 = FUSE: FUSE 10A 60V FAST SMD; Chkd/date: RAGESH/151010; Crtd /date: MAZHAR/220907; Distributor_name: DIGIKEY; Distributor_part_number: TR2/1025FA10-R-ND; Height: 2.90MM; Mfr_name: COOPER BUSSMANN; Mfr_part_number: 1025FA10-R; Mistral Part No: 130009030821-R; Package: SMD; Project: SMART VIEW_NVR; RoHS: RoHS; Voltage: 60V; Datasheet: Y:\MIS_DATABASE\DATASHEETS\MISC\FUSE\1025FA-SER.PDF
J6 = CON_PWRJACK3_PJ-063BH: CON POWER JACK 2POS MALE RT TH; Chkd/date: MANIRAJA/100320; Crtd /date: ALVY/060320; Custom_Duty: 24%; Customs_HS_Code: 85369090; Distributor_name: DIGIKEY; Distributor_part_number: CP-063AH-ND; Footprint Path: Y:\MIS_DATABASE\Library\ALTIUM_TOOL\PCB_FOOTPRINTS\Altium_Footprint_Lib.PcbLib; Height: 9.00MM; Library Path: Y:\MIS_DATABASE\Library\ALTIUM_TOOL\SCHEMATICS_PARTS\MS_CONNECTOR_Library.schlib; Mfr_name: CUI INC; Mfr_part_number: PJ-063AH; Mistral Part No: 150020030011-R; Package: THRU-HOLE; Part_type: CONNECTOR\JACK; Project: TPR12_SVB; RoHS: RoHS; Temperature: -25°C+85°C; Tolerance: NA; Voltage: NA; Wattage: NA; Weight: 2400mg; Datasheet: Y:\MIS_DATABASE\DATASHEETS\CONNECTORS\PJ-063AH.PDF
LD5 = DIODE_LED: DIODE LED RED SMD; Chkd/date: MANIRAJA/180820; Crtd /date: ALVY/180820; Custom_Duty: 24%; Customs_HS_Code: 85439000; Distributor_name: DIGIKEY; Distributor_part_number: 732-4984-1-ND; Footprint Path: Y:\MIS_DATABASE\Library\ALTIUM_TOOL\PCB_FOOTPRINTS\Altium_Footprint_Lib.PcbLib; Height: 0.80MM; Library Path: Y:\MIS_DATABASE\Library\ALTIUM_TOOL\SCHEMATICS_PARTS\MS_OPTO_Library.schlib; Mfr_name: WURTH ELECTRONICS; Mistral Part No: 130020080013-R; Package: SMD; Part_type: OPTO\LED; Project: AM64x_EVM_BRD; RoHS: RoHS; Temperature: -40°C+85°C; Tolerance: NA; Voltage: NA; Wattage: NA; Weight: 25mg; Datasheet: Y:\MIS_DATABASE\DATASHEETS\DISCRETES\LEDS\150080RS75000.PDF
Q1 Q2 Q5-Q7 Q11 = MOSFET_BSS138LT1G: IC MOSFET N-CHANNEL 50V 200mA SOT23-3; Chkd/date: MANIRAJA/250219; Crtd /date: JEBRAN/060416; Custom_Duty: 15%; Customs_HS_Code: 85423100; Distributor_name: DIGIKEY; Distributor_part_number: BSS138LT1GOSCT-ND; Footprint Path: Y:\MIS_DATABASE\Library\ALTIUM_TOOL\PCB_FOOTPRINTS\Altium_Footprint_Lib.PcbLib; Height: 1.11MM; Library Path: Y:\MIS_DATABASE\Library\ALTIUM_TOOL\SCHEMATICS_PARTS\MS_MOSFET_Library.schlib; Library Ref: MOSFET_BSS138W; Mfr_name: ON SEMICONDUCTOR; Mistral Part No: 142016040001-R; Package: SOT23-3; Part_type: ICS\POWER\MOSFET; Project: LRDE_ABCM; RoHS: RoHS; Temperature: -55°C+150°C; Tolerance: NA; Voltage: NA; Wattage: NA; Weight: 8mg; Datasheet: Y:\MIS_DATABASE\DATASHEETS\DISCRETES\TRANSISTORS_FETS\BSS138LT1G.PDF
R64 = RESISTOR: RES 10K 2/3W 5% 1206; Chkd/date: VASANTHA/101015; Crtd /date: VASANTHA/101015; Custom_Duty: 15%; Customs_HS_Code: 85332119; Distributor_name: DIGIKEY; Distributor_part_number: P10KALCT-ND; Footprint Path: Y:\MIS_DATABASE\Library\ALTIUM_TOOL\PCB_FOOTPRINTS\Altium_Footprint_Lib.PcbLib; Height: 0.70MM; Library Path: Y:\MIS_DATABASE\Library\ALTIUM_TOOL\SCHEMATICS_PARTS\MS_DISCRETE_Library.schlib; Mfr_name: PANASONIC-ECG; Mfr_part_number: ERJ-P08J103V; Mistral Part No: 110015090016-R; Package: 1206; Part_type: RESISTORS\FIXED; Project: GALILEO_EVM; RoHS: RoHS; Temperature: -55°C+155°C; Tolerance: 5%; Voltage: NA; Wattage: 2/3W; Weight: 10mg; Datasheet: Y:\MIS_DATABASE\DATASHEETS\RESISTORS\ERJ-PA_P0-SER.PDF
R80 = RESISTOR: RES 1K 1/10W 1% 0402; Chkd/date: VASANTHA/281216; Crtd /date: MAZHAR/150506; Custom_Duty: 15%; Customs_HS_Code: 85332119; Distributor_name: DIGIKEY; Distributor_part_number: P1.00KLCT-ND; Footprint Path: Y:\MIS_DATABASE\Library\ALTIUM_TOOL\PCB_FOOTPRINTS\Altium_Footprint_Lib.PcbLib; Height: 0.40MM; Library Path: Y:\MIS_DATABASE\Library\ALTIUM_TOOL\SCHEMATICS_PARTS\MS_DISCRETE_Library.schlib; Mfr_name: PANASONIC-ECG; Mfr_part_number: ERJ-2RKF1001X; Mistral Part No: 110009030411-R; Package: 0402; Part_type: RESISTORS\FIXED; Project: VOCERA; RoHS: RoHS; Temperature: -55°C+155°C; Tolerance: 1%; Voltage: NA; Wattage: 1/10W; Weight: 0.8mg; Datasheet: Y:\MIS_DATABASE\DATASHEETS\RESISTORS\PAN-ERJSER_NOV17.PDF
R566 = RESISTOR: RES 1M 1/10W 5% 0603; Chkd/date: VASANTHA/060217; Crtd /date: USMAN/111207; Custom_Duty: 15%; Customs_HS_Code: 85332119; Distributor_name: DIGIKEY; Distributor_part_number: P1.0MGCT-ND; Footprint Path: Y:\MIS_DATABASE\Library\ALTIUM_TOOL\PCB_FOOTPRINTS\Altium_Footprint_Lib.PcbLib; Height: 0.55MM; Library Path: Y:\MIS_DATABASE\Library\ALTIUM_TOOL\SCHEMATICS_PARTS\MS_DISCRETE_Library.schlib; Mfr_name: PANASONIC-ECG; Mfr_part_number: ERJ-3GEYJ105V; Mistral Part No: 110009030413-R; Package: 0603; Part_type: RESISTORS\FIXED; Project: BSN; RoHS: RoHS; Temperature: -55°C+155°C; Tolerance: 5%; Voltage: NA; Wattage: 1/10W; Weight: 2mg; Datasheet: Y:\MIS_DATABASE\DATASHEETS\RESISTORS\PAN-ERJSER_NOV17.PDF
TP2 TP3 TP5 TP26 TP31 TP34 = TESTPOINT: ACCESSORIE PC TEST POINT; Chkd/date: VASANTHA/121216; Crtd /date: MANIRAJA/121216; Custom_Duty: NA; Customs_HS_Code: NA; Distributor_name: DIGIKEY; Distributor_part_number: 36-5002-ND; Footprint Path: Y:\MIS_DATABASE\Library\ALTIUM_TOOL\PCB_FOOTPRINTS\Altium_Footprint_Lib.PcbLib; Height: 4.57MM; Library Path: Y:\MIS_DATABASE\Library\ALTIUM_TOOL\SCHEMATICS_PARTS\MS_DISCRETE_Library.schlib; Mfr_name: KEYSTONE; Mistral Part No: 160016120008-R; Package: NA; Part_type: ACCESSORIES; Project: EPOS_EVM; RoHS: RoHS; Temperature: NA; Tolerance: NA; Voltage: NA; Wattage: NA; Weight: NA; Datasheet: Y:\MIS_DATABASE\DATASHEETS\MISC\ACCESSORIES\5002.PDF
TP81 = TESTPOINT: TESTPOINT 1.0MM DRILL PTH; Chkd/date: MAZHAR/271211; Crtd /date: SHREESHAIL/041005; Distributor_name: NA; Distributor_part_number: NA; Height: NA; Mfr_name: LOCAL; Mistral Part No: 130009030938; Package: THRU-HOLE; Project: HSE; Datasheet: NA

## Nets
DGND: C1.2 C2.2 C3.2 C4.1 C7.1 C8.2 C23.1 C24.1 C56.2 C147.2 C207.1 C410.1 C455.2 C462.1 C463.1 C470.1 C473.2 C474.2 C478.2 C492.2 C493.2 D1.2(ANODE) D2.2(A) J3.1 J3.5 J3.8 J3.9 J3.12 J3.13 J3.16 J3.20 J6.2 J12.2 J31.2 J32.2 J36.8 LD6.1(CATHODE) Q1.2(S) Q2.2(S) Q5.2(S) Q6.2(S) Q7.2(S) Q11.2(S) R8.1 R9.1 R16.2 R23.2 R401.1 R402.1 R413.1 R531.1 R541.1 R566.2 TP2.1(TP) TP3.1(TP) TP5.1(TP) TP26.1(TP) TP31.1(TP) TP34.1(TP) U3.2(GND) U4.2(GND) U23.A1(VSS) U23.A5(VSS) U23.A6(VSS) U23.A21(VSS) U23.AA1(VSS) U23.AA15(VSS) U23.AA18(VSS) U23.AA21(VSS) U23.C3(VSS) U23.C10(VSS) U23.C15(VSS) U23.D1(VSS) U23.E11(VSS) U23.E13(VSS) U23.F8(VSS) U23.F10(VSS) U23.F15(VSS) U23.G1(VSS) U23.G3(VSS) U23.G7(VSS) U23.G9(VSS) U23.G16(VSS) U23.H6(VSS) U23.H8(VSS) U23.H11(VSS) U23.H20(VSS) U23.H21(VSS) U23.J7(VSS) U23.J9(VSS) U23.J14(VSS) U23.J16(VSS) U23.K6(VSS) U23.K8(VSS) U23.L1(VSS) U23.L3(VSS) U23.L7(VSS) U23.L9(VSS) U23.L16(VSS) U23.M6(VSS) U23.M8(VSS) U23.M10(VSS) U23.M12(VSS) U23.N7(VSS) U23.N9(VSS) U23.N11(VSS) U23.N13(VSS) U23.N15(VSS) U23.P1(VSS) U23.P6(VSS) U23.P8(VSS) U23.P10(VSS) U23.P18(VSS) U23.R7(VSS) U23.R9(VSS) U23.R12(VSS) U23.T8(VSS) U23.T10(VSS) U23.T11(VSS) U23.T15(VSS) U23.T16(VSS) U23.U3(VSS) U23.V17(VSS) U23.W10(VSS) U23.W18(VSS) U23.Y14(VSS) U23.Y17(VSS) U23.Y19(VSS) U34.8(~{G}) U34.16(GND) U67.8(GND) U83.5(VSS) U99.2(GND) ; also on sheet 2 3 4 5 10 11 12 13 14 15 16 17 18 19 20 21 22 23 24 25 26 27 28 29 30 39 40
VCC1V1_PG: R136.2 ; also on sheet 16
VCC1V2_PG: R14.2 ; also on sheet 15
VCC2V5_PG: R217.2 ; also on sheet 16
VCC_3V3_SYS: C147.1 C207.2 C410.2 C470.2 FB1.1 R15.2 R211.2 R212.2 R305.2 R353.1 R354.1 R357.1 R358.1 R360.2 R365.2 R381.1 R382.1 R383.1 R384.1 R394.2 R395.2 R398.2 R399.2 R418.1 R419.1 R420.1 R421.1 R516.1 U34.1(VCC) U67.16(VCC) U83.8(VCC) U99.5(VIN) ; also on sheet 2 5 10 11 12 13 14 15 16 17 18 19 20 21 23 24 25 26 27 29 30 39 40
VCC_5V0: FB2.1 ; also on sheet 4 17 18 20 25
VCC_CAN: C23.2 C24.2 FB2.2 U3.3(VCC) U4.3(VCC)
VCC_CORE_PG: R312.2 ; also on sheet 15 17
VCC_LCD: C474.1 J36.1 TP100.1(TP)
VDD1V8_PG: R127.2 ; also on sheet 15
VDD_0V85_PG: R20.2 ; also on sheet 15
VDD_2V8: C463.2 J36.7 R538.1 ; also on sheet 16
VDDA_ADC: C4.2 C7.2 J3.4 J3.17 ; also on sheet 4
VDDB_3V3_DISPLAY: C455.1 C462.2 J36.10 U99.1(VOUT)
ADC0_AIN0: J3.15 U23.G20(ADC0_AIN0)
ADC0_AIN1: J3.14 U23.F20(ADC0_AIN1)
ADC0_AIN2: J3.6 U23.E21(ADC0_AIN2)
ADC0_AIN3: J3.18 U23.D20(ADC0_AIN3)
ADC0_AIN4: J3.10 U23.G21(ADC0_AIN4)
ADC0_AIN5: J3.7 U23.F21(ADC0_AIN5)
ADC0_AIN6: J3.3 U23.F19(ADC0_AIN6)
ADC0_AIN7: J3.11 U23.E20(ADC0_AIN7)
C1N: C460.1 J36.11
C1P: C460.2 J36.12
C2N: C454.1 J36.13
C2P: C454.2 J36.14
CAN_MUX_OE: R23.1 U67.15(~{OE})
CAN_MUX_SEL: R16.1 U67.1(S) ; also on sheet 13
CLKOUT0: R345.2 ; also on sheet 11
DISPLAY_VDDB3V3_ON: R538.2 U99.4(ON)
GPIO1_43_INTn: U23.C13(SPI0_CS1) ; also on sheet 25
GPIO_OLED_RESETn: J36.6 R531.2 ; also on sheet 13
HSE_MCAN0_RX/UART4_TXD: U67.3(1B2) ; also on sheet 18
HSE_MCAN0_TX/UART4_RXD: U67.6(2B2) ; also on sheet 18
HSE_MCAN1_RX/I2C3_SDA: U67.10(3B2) ; also on sheet 18
HSE_MCAN1_TX/I2C3_SCL: U67.13(4B2) ; also on sheet 18
IFORCE: TP71.1(TP) U23.H16(IFORCE)
LED1: LD16.1(CATHODE) U34.3(DRAIN0)
LED2: LD17.1(CATHODE) U34.4(DRAIN1)
LED3: LD18.1(CATHODE) U34.5(DRAIN2)
LED4: LD19.1(CATHODE) U34.6(DRAIN3)
LED5: LD14.1(CATHODE) U34.11(DRAIN4)
LED6: LD13.1(CATHODE) U34.12(DRAIN5)
LED7: LD12.1(CATHODE) U34.13(DRAIN6)
LED8: LD11.1(CATHODE) U34.14(DRAIN7)
MAIN: F1.1 J6.1
MCAN0_H: J31.1 R4.1 U4.7(CANH)
MCAN0_L: J31.3 R5.2 U4.6(CANL)
MCAN0_RX: J9.1 R220.1 U67.2(1B1)
MCAN0_RX/HSE: U23.B17(MCAN0_RX) U67.4(1A)
MCAN0_STB_3V3: R9.2 U4.8(STB) ; also on sheet 13
MCAN0_T: C2.1 R4.2 R5.1
MCAN0_TX: J9.2 R221.1 U67.5(2B1)
MCAN0_TX/HSE: U23.A17(MCAN0_TX) U67.7(2A)
MCAN1_H: J32.1 R2.1 U3.7(CANH)
MCAN1_L: J32.3 R3.2 U3.6(CANL)
MCAN1_RX: J10.1 R222.1 U67.11(3B1)
MCAN1_RX/HSE: U23.D17(MCAN1_RX) U67.9(3A)
MCAN1_STB_3V3: R8.2 U3.8(STB) ; also on sheet 13
MCAN1_T: C1.1 R2.2 R3.1
MCAN1_TX: J10.2 R223.1 U67.14(4B1)
MCAN1_TX/HSE: U23.C17(MCAN1_TX) U67.12(4A)
SHIELD: C478.1 J6.SH1 J6.SH2 R566.1
SoC_I2C0_SCL: R358.2 R598.1 ; also on sheet 10 13 18
SoC_I2C0_SCL_RC: C492.1 R598.2 U23.A18(I2C0_SCL)
SoC_I2C0_SDA: R354.2 R599.1 ; also on sheet 10 13 18
SoC_I2C0_SDA_RC: C493.1 R599.2 U23.B18(I2C0_SDA)
SoC_I2C1_SCL: J36.5 R353.2 U23.C18(I2C1_SCL) U34.15(SCL) ; also on sheet 5 10 13 14 30
SoC_I2C1_SDA: J36.4 R357.2 U23.B19(I2C1_SDA) U34.2(SDA) ; also on sheet 5 10 13 14 30
SOC_MAIN_UART0_CTS_3V3: U23.B16(UART0_CTSN) ; also on sheet 23
SOC_MAIN_UART0_RTS_3V3: U23.A16(UART0_RTSN) ; also on sheet 23
SOC_MAIN_UART0_RX_3V3: U23.D15(UART0_RXD) ; also on sheet 23
SOC_MAIN_UART0_TX_3V3: U23.C16(UART0_TXD) ; also on sheet 23
SOC_MAIN_UART1_RX_3V3: U23.E15(UART1_RXD) ; also on sheet 23
SOC_MAIN_UART1_TX_3V3: U23.E14(UART1_TXD) ; also on sheet 23
SOC_MAIN_UART3_RX_3V3: U23.D16(UART1_CTSN) ; also on sheet 23
SOC_MAIN_UART3_TX_3V3: U23.E16(UART1_RTSN) ; also on sheet 23
SoC_OSC0: TP65.1(TP) U23.G13(ATEST0)
SOC_SPI0_CLK: R395.1 TP77.1(TP) U23.D13(SPI0_CLK) U83.2(CLK)
SOC_SPI0_CS0: R399.1 TP80.1(TP) U23.D12(SPI0_CS0) U83.1(CS)
SOC_SPI0_MISO: R398.1 TP79.1(TP) U23.A14(SPI0_D1) U83.4(DO)
SOC_SPI0_MOSI: R394.1 TP76.1(TP) U23.A13(SPI0_D0) U83.3(DI)
SOC_SPI1_CLK: U23.C14(SPI1_CLK) ; also on sheet 18
SOC_SPI1_CS0: U23.B14(SPI1_CS0) ; also on sheet 18
SOC_SPI1_CS1: U23.D14(SPI1_CS1) ; also on sheet 18
SOC_SPI1_MISO: U23.A15(SPI1_D1) ; also on sheet 18
SOC_SPI1_MOSI: U23.B15(SPI1_D0) ; also on sheet 18
SoC_VSENSE: TP30.1(TP) U23.D21(VSENSE)
SYNC1_OUT_TP: J12.1 U23.D18(ECAP0_IN_APWM_OUT)
VCOMH: C473.1 J36.2
VIO_CAN: C3.1 C8.1 FB1.2 U3.5(VIO) U4.5(VIO)
VMAIN: C56.1 D3.3(K) R80.2 TP81.1(TP) ; also on sheet 4 5 16 17
N17247526: LD16.2(ANODE) R421.2
N17247539: LD17.2(ANODE) R420.2
N17247599: LD18.2(ANODE) R419.2
N17247637: LD19.2(ANODE) R418.2
N17247662: LD14.2(ANODE) R381.2
N17247701: LD13.2(ANODE) R382.2
N17247743: LD12.2(ANODE) R383.2
N17247786: LD11.2(ANODE) R384.2
N17248427: R413.2 U34.7(A2)
N17248432: R402.2 U34.10(A1)
N17248439: R401.2 U34.9(A0)
N18546005: D1.1(CATHODE) D3.1(A1) D3.2(A2) F1.2 R64.1
N18546027: LD5.1(CATHODE) R64.2
N18546044: D2.1(K) LD5.2(ANODE)
N25294505: LD6.2(ANODE) R80.1
N25657725: R345.1 U23.A19(EXT_REFCLK1)
N25657961: J36.3 R541.2
N25658118: R516.2 U99.3(OC)
N26118637: R221.2 U4.1(TXD)
N26118639: R220.2 U4.4(RXD)
N26120249: R223.2 U3.1(TXD)
N26120251: R222.2 U3.4(RXD)
N26145534: Q5.1(G) R312.1
N26145544: LD7.2(ANODE) R305.1
N26145600: Q2.1(G) R20.1
N26145606: LD2.2(ANODE) R211.1
N26145666: Q1.1(G) R14.1
N26145672: LD3.2(ANODE) R15.1
N26145732: Q7.1(G) R136.1
N26145738: LD10.2(ANODE) R365.1
N26145798: Q6.1(G) R127.1
N26145804: LD8.2(ANODE) R360.1
N26145856: Q11.1(G) R217.1
N26145862: LD1.2(ANODE) R212.1
N28118242: LD7.1(CATHODE) Q5.3(D)
N28118245: LD2.1(CATHODE) Q2.3(D)
N28118248: LD3.1(CATHODE) Q1.3(D)
N28118251: LD10.1(CATHODE) Q7.3(D)
N28118254: LD8.1(CATHODE) Q6.3(D)
N28118257: LD1.1(CATHODE) Q11.3(D)

Not connected (* = marked no-connect by the designer): J3 2* 19*; J36 9*; U83 6(NC1)* 7(NC2)*

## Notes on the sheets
sheet 6
- HSE/CAN MUX
- LPF Designed for 25MHz Cutoff
  Have to change resistor and capacitor values accordingly
- CAN INTERFACE
- DISPLAY
- DISPLAY CONNECTOR
- 120E
- 16V CAP
- 120E
- Off Page Connections
- From Debounce Circuit
- SPI EEPROM
- From IO Expander
- To HSE Connector
- EEPROM
- To Clock Buffer
- To FT4232 Bridge
sheet 7
- ETHERNET LED's
- I2C ADDRESS: 0x60
- ADC CONNECTOR
- Off Page Connections
sheet 8
- MAIN INPUT 12V DC
- VCC = 12V
  ICC max = 8A
- RED
- Condition
- LED Status(LD1)
- Reverse Voltage
- ON
- POWER INDICATION LED's
- Off Page Connections
- Ground test points
sheet 9
- SoC POWER - VSS
